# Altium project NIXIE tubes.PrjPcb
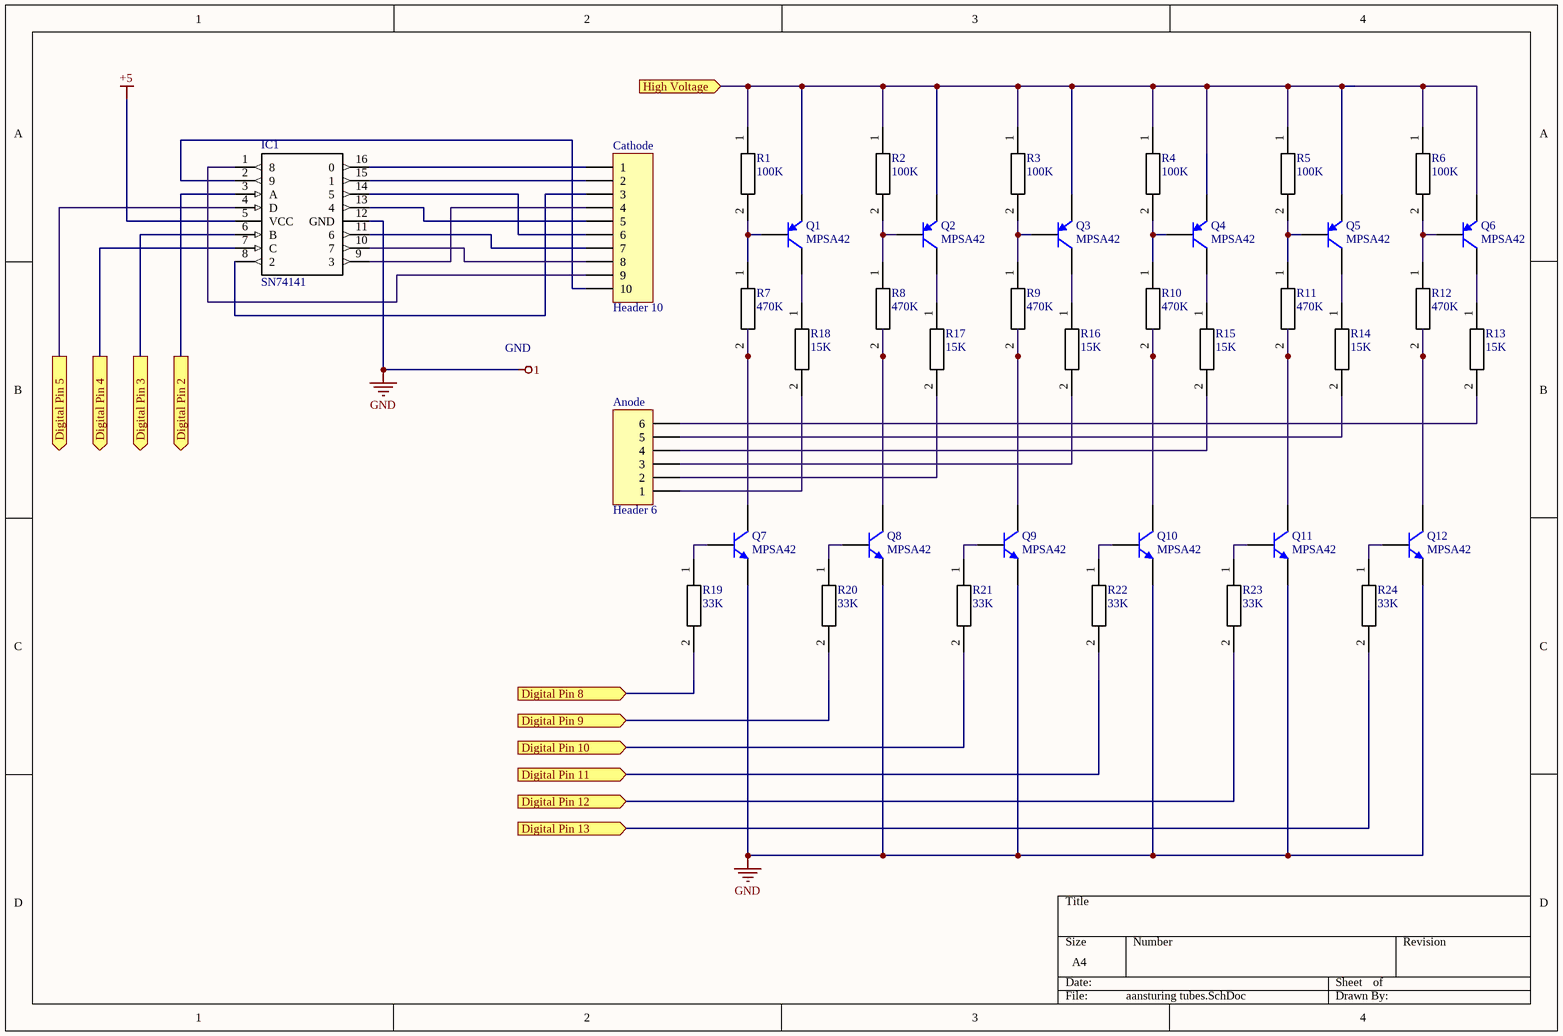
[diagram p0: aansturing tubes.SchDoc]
4 sheets, 89 parts. Net scope: flat (ports and power ports of the same name join across sheets).
Board files: PCB1-sturing.PcbDoc, PCB2-Tubes.PcbDoc
Sheets:
  aansturing tubes.SchDoc
  high voltage.SchDoc
  low voltage + controller.SchDoc
  Tubes.SchDoc

## Sheet aansturing tubes.SchDoc
size A4

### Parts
Anode  Header 6  [HDR1X6]
Cathode  Header 10  [HDR1X10]
IC1  SN74141  [DIP787W53P279L2176H508Q16N]
Q1  MPSA42  [TO-92A]
Q2  MPSA42  [TO-92A]
Q3  MPSA42  [TO-92A]
Q4  MPSA42  [TO-92A]
Q5  MPSA42  [TO-92A]
Q6  MPSA42  [TO-92A]
Q7  MPSA42  [TO-92A]
Q8  MPSA42  [TO-92A]
Q9  MPSA42  [TO-92A]
Q10  MPSA42  [TO-92A]
Q11  MPSA42  [TO-92A]
Q12  MPSA42  [TO-92A]
R1  100K  [RESC3116X65N]
R2  100K  [RESC3116X65N]
R3  100K  [RESC3116X65N]
R4  100K  [RESC3116X65N]
R5  100K  [RESC3116X65N]
R6  100K  [RESC3116X65N]
R7  470K  [RESC3116X65N]
R8  470K  [RESC3116X65N]
R9  470K  [RESC3116X65N]
R10  470K  [RESC3116X65N]
R11  470K  [RESC3116X65N]
R12  470K  [RESC3116X65N]
R13  15K  [RESAD1590W60L630D240]
R14  15K  [RESAD1590W60L630D240]
R15  15K  [RESAD1590W60L630D240]
R16  15K  [RESAD1590W60L630D240]
R17  15K  [RESAD1590W60L630D240]
R18  15K  [RESAD1590W60L630D240]
R19  33K  [RESC3116X65N]
R20  33K  [RESC3116X65N]
R21  33K  [RESC3116X65N]
R22  33K  [RESC3116X65N]
R23  33K  [RESC3116X65N]
R24  33K  [RESC3116X65N]

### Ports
Digital Pin 2 (out), Digital Pin 3 (out), Digital Pin 4 (out), Digital Pin 5 (out), Digital Pin 8 (in), Digital Pin 9 (in), Digital Pin 10 (in), Digital Pin 11 (in), Digital Pin 12 (in), Digital Pin 13 (in), High Voltage (in)

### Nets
1: IC1.12(GND) Q7.1(E) Q8.1(E) Q9.1(E) Q10.1(E) Q11.1(E) Q12.1(E)  [also labelled GND]
+5: IC1.5(VCC)
NetAnode_1: Anode.1 R18.2
NetAnode_2: Anode.2 R17.2
NetAnode_3: Anode.3 R16.2
NetAnode_4: Anode.4 R15.2
NetAnode_5: Anode.5 R14.2
NetAnode_6: Anode.6 R13.2
NetC1_1: Q1.1(E) Q2.1(E) Q3.1(E) Q4.1(E) Q5.1(E) Q6.1(E) R1.1 R2.1 R3.1 R4.1 R5.1 R6.1 ; port High Voltage
NetCathode_1: Cathode.1 IC1.16(0)
NetCathode_2: Cathode.2 IC1.15(1)
NetCathode_3: Cathode.3 IC1.8(2)
NetCathode_4: Cathode.4 IC1.9(3)
NetCathode_5: Cathode.5 IC1.13(4)
NetCathode_6: Cathode.6 IC1.14(5)
NetCathode_7: Cathode.7 IC1.11(6)
NetCathode_8: Cathode.8 IC1.10(7)
NetCathode_9: Cathode.9 IC1.1(8)
NetCathode_10: Cathode.10 IC1.2(9)
NetIC1_3: IC1.3(A) ; port Digital Pin 2
NetIC1_4: IC1.4(D) ; port Digital Pin 5
NetIC1_6: IC1.6(B) ; port Digital Pin 3
NetIC1_7: IC1.7(C) ; port Digital Pin 4
NetIC3_14: R19.2 ; port Digital Pin 8
NetIC3_15: R20.2 ; port Digital Pin 9
NetIC3_16: R21.2 ; port Digital Pin 10
NetIC3_17: R22.2 ; port Digital Pin 11
NetIC3_18: R23.2 ; port Digital Pin 12
NetIC3_19: R24.2 ; port Digital Pin 13
NetQ1_2: Q1.2(B) R1.2 R7.1
NetQ1_3: Q1.3(C) R18.1
NetQ2_2: Q2.2(B) R2.2 R8.1
NetQ2_3: Q2.3(C) R17.1
NetQ3_2: Q3.2(B) R3.2 R9.1
NetQ3_3: Q3.3(C) R16.1
NetQ4_2: Q4.2(B) R4.2 R10.1
NetQ4_3: Q4.3(C) R15.1
NetQ5_2: Q5.2(B) R5.2 R11.1
NetQ5_3: Q5.3(C) R14.1
NetQ6_2: Q6.2(B) R6.2 R12.1
NetQ6_3: Q6.3(C) R13.1
NetQ7_2: Q7.2(B) R19.1
NetQ7_3: Q7.3(C) R7.2
NetQ8_2: Q8.2(B) R20.1
NetQ8_3: Q8.3(C) R8.2
NetQ9_2: Q9.2(B) R21.1
NetQ9_3: Q9.3(C) R9.2
NetQ10_2: Q10.2(B) R22.1
NetQ10_3: Q10.3(C) R10.2
NetQ11_2: Q11.2(B) R23.1
NetQ11_3: Q11.3(C) R11.2
NetQ12_2: Q12.2(B) R24.1
NetQ12_3: Q12.3(C) R12.2

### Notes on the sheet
- GND

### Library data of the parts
Anode = Header 6: Header, 6-Pin
Cathode = Header 10: Header, 10-Pin
IC1 = SN74141: Integrated Circuit; Manufacturer_Name: Texas Instruments
Q1-Q6 = 2N3906: PNP General Purpose Amplifier
Q7-Q12 = 2N3904: NPN General Purpose Amplifier
R1-R12 R19-R24 = RC1206JR-07_10KL: Resistor; Manufacturer_Name: YAGEO (PHYCOMP); Manufacturer_Part_Number: RC1206JR-07 10KL
R13-R18 = MF0207FTE52-10K: Resistor; Manufacturer_Name: YAGEO (PHYCOMP)

## Sheet high voltage.SchDoc
size A4
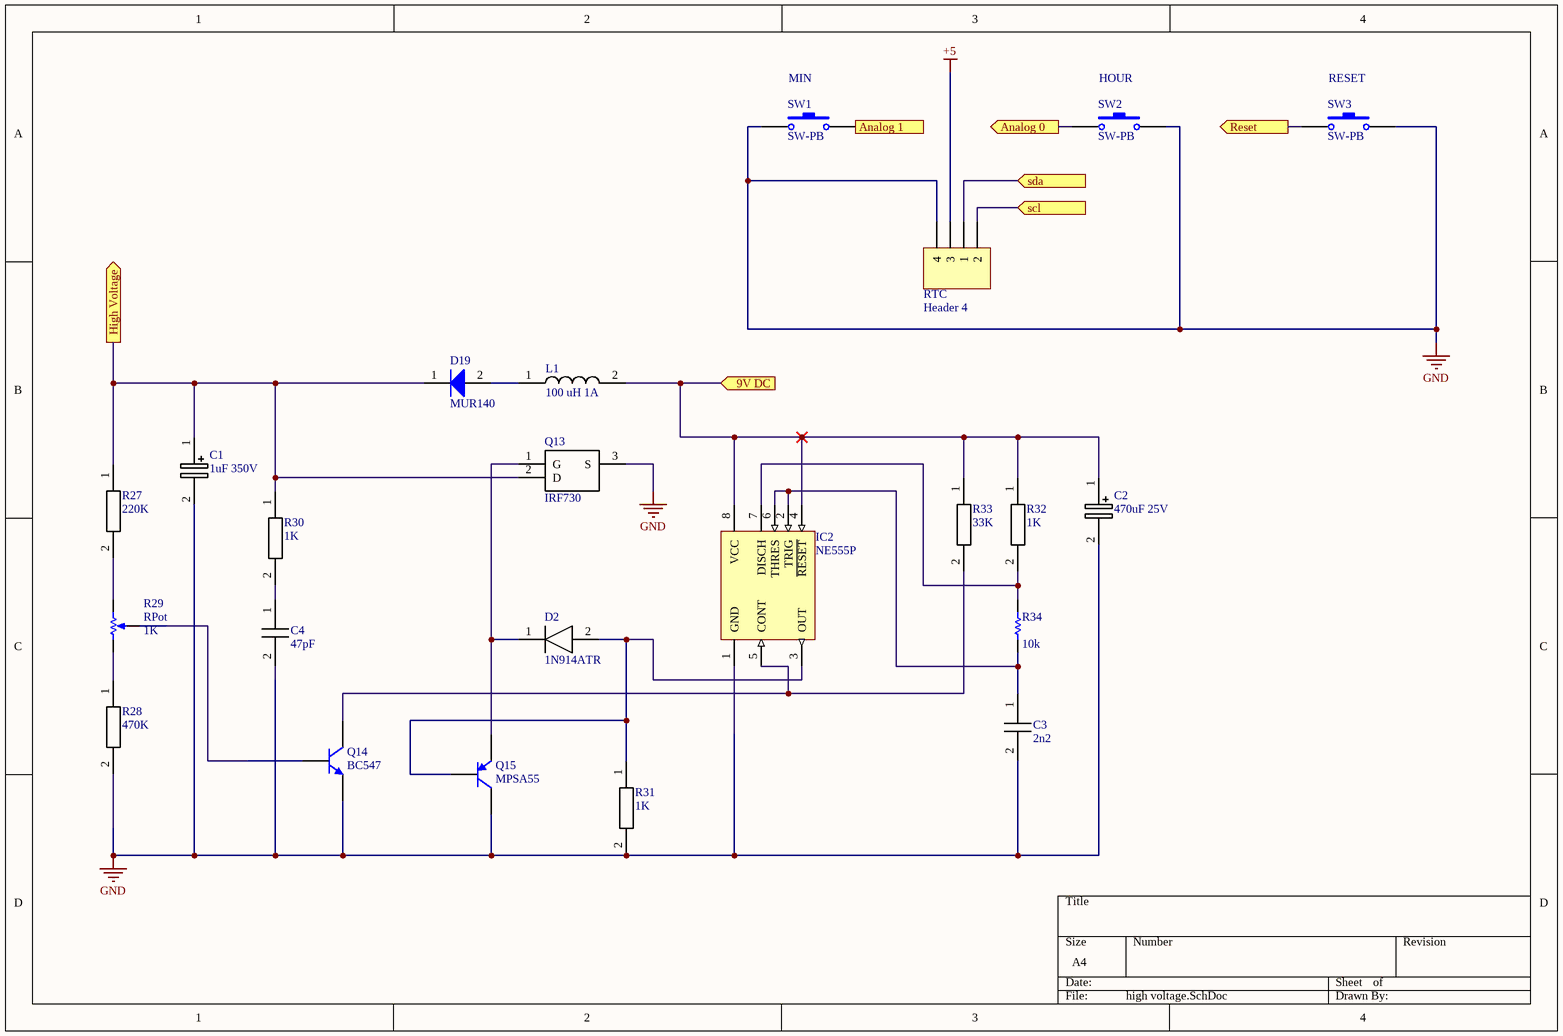
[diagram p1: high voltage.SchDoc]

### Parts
C1  1uF 350V  [CAPPRD350W52D800H1300]
C2  470uF 25V  [CAPPRD350W52D800H1300]
C3  2n2  [CAPC3216X95N]
C4  47pF  [CAPC3216X95N]
D2  1N914ATR  [DIOAD1068W53L380D172]
D19  MUR140  [ONSC-AXIAL_LEAD-2-59-10_P]
IC2  NE555P  [P0008A]
L1  100 uH 1A  [WE-TI_8012B89]
Q13  IRF730  [TO254P465X1024X1989-3P]
Q14  BC547  [TO-92A]
Q15  MPSA55  [TO-92A]
R27  220K  [RESAD1590W60L630D240]
R28  470K  [RESAD1590W60L630D240]
R29  RPot  value 1K  [VR5]
R30  1K  [RESAD1590W60L630D240]
R31  1K  [RESAD1590W60L630D240]
R32  1K  [RESAD1590W60L630D240]
R33  33K  [RESAD1590W60L630D240]
R34  value 10k  [AXIAL-0.3]  (hidden comment: Res1)
RTC  Header 4  [HDR1X4]
SW1  SW-PB  [SPST-2]
SW2  SW-PB  [SPST-2]
SW3  SW-PB  [SPST-2]

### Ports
9V DC (in), Analog 0 (out), Analog 1 (out), High Voltage (out), Reset (out), scl (in), sda (in)

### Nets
+5: RTC.3
GND: C1.2(-) C2.2(-) C3.2 C4.2 IC2.1(GND) Q13.3(S) Q14.1(E) Q15.3(C) R28.2 R31.2 RTC.4 SW1.1 SW2.2 SW3.2  [project net 1]
NetC1_1: C1.1(+) D19.1(K) Q13.2(D) R27.1 R30.1 ; port High Voltage
NetC2_1: C2.1(+) IC2.4(~{RESET}) IC2.8(VCC) L1.2 R32.1 R33.1 ; port 9V DC
NetC3_1: C3.1 IC2.2(TRIG) IC2.6(THRES) R34.1
NetC4_1: C4.1 R30.2
NetD2_1: D2.1(K) Q13.1(G) Q15.1(E)
NetD2_2: D2.2(A) IC2.3(OUT) Q15.2(B) R31.1
NetD19_2: D19.2(A) L1.1
NetIC2_5: IC2.5(CONT) Q14.3(C) R33.2
NetIC2_7: IC2.7(DISCH) R32.2 R34.2
NetIC3_1: SW3.1 ; port Reset
NetIC3_23: SW1.2 ; port Analog 1
NetIC3_24: SW2.1 ; port Analog 0
NetIC3_27: RTC.1 ; port sda
NetIC3_28: RTC.2 ; port scl
NetQ14_2: Q14.2(B) R29.3(TAP)
NetR27_2: R27.2 R29.2(BOT)
NetR28_1: R28.1 R29.1(TOP)

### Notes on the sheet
- (near SW1) MIN
- (near SW2) HOUR
- (near SW3) RESET

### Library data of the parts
C1 C2 = 860131274001: Capacitor Polarised; Manufacturer_Name: Wurth Elektronik
C3 = CC1206KRX7R9BB471: Capacitor; Manufacturer_Name: YAGEO (PHYCOMP)
C4 = CC1206JRNPO9BN220: Capacitor; Manufacturer_Name: YAGEO (PHYCOMP)
D2 = 1N914ATR: Diode; Manufacturer_Name: Fairchild Semiconductor
D19 = CMP-0902-00130-1: SWITCHMODE(TM) Power Rectifier, 2-Pin Axial_Lead, Pb-Free, Bulk Box; Manufacturer: On Semiconductor; IFSM Max (A): 35; Type: Ultrafast; VRRM Max (V): 400
IC2 = CMP-2000-04954-1: Precision Timer, 4.5 to 16 V, 0 to 70 degC, 8-Pin DIP, Pb-Free, Tube; Manufacturer: TexasInstruments; Maximum High Level Output Current: -200mA; Number of Internal Timers: 1; Operating Supply Voltage: 5; Maximum Low Level Output Current: 200mA; Rad Hard: No
L1 = 744743101: Inductor; Manufacturer_Name: Wurth Elektronik
Q13 = IRF730: Transistor; Manufacturer_Name: STMicroelectronics
Q14 = 2N3904: NPN General Purpose Amplifier
Q15 = 2N3906: PNP General Purpose Amplifier
R27 R28 R30-R33 = MF0207FTE52-10K: as R13 on sheet aansturing tubes
R29 = RPot: Potentiometer; Sim Note: Enter the Resistance value and the set point into parameter fields.; Set Position: 0.5
R34 = Res1: Resistor
RTC = Header 4: Header, 4-Pin
SW1-SW3 = SW-PB: Switch

## Sheet low voltage + controller.SchDoc
size A4
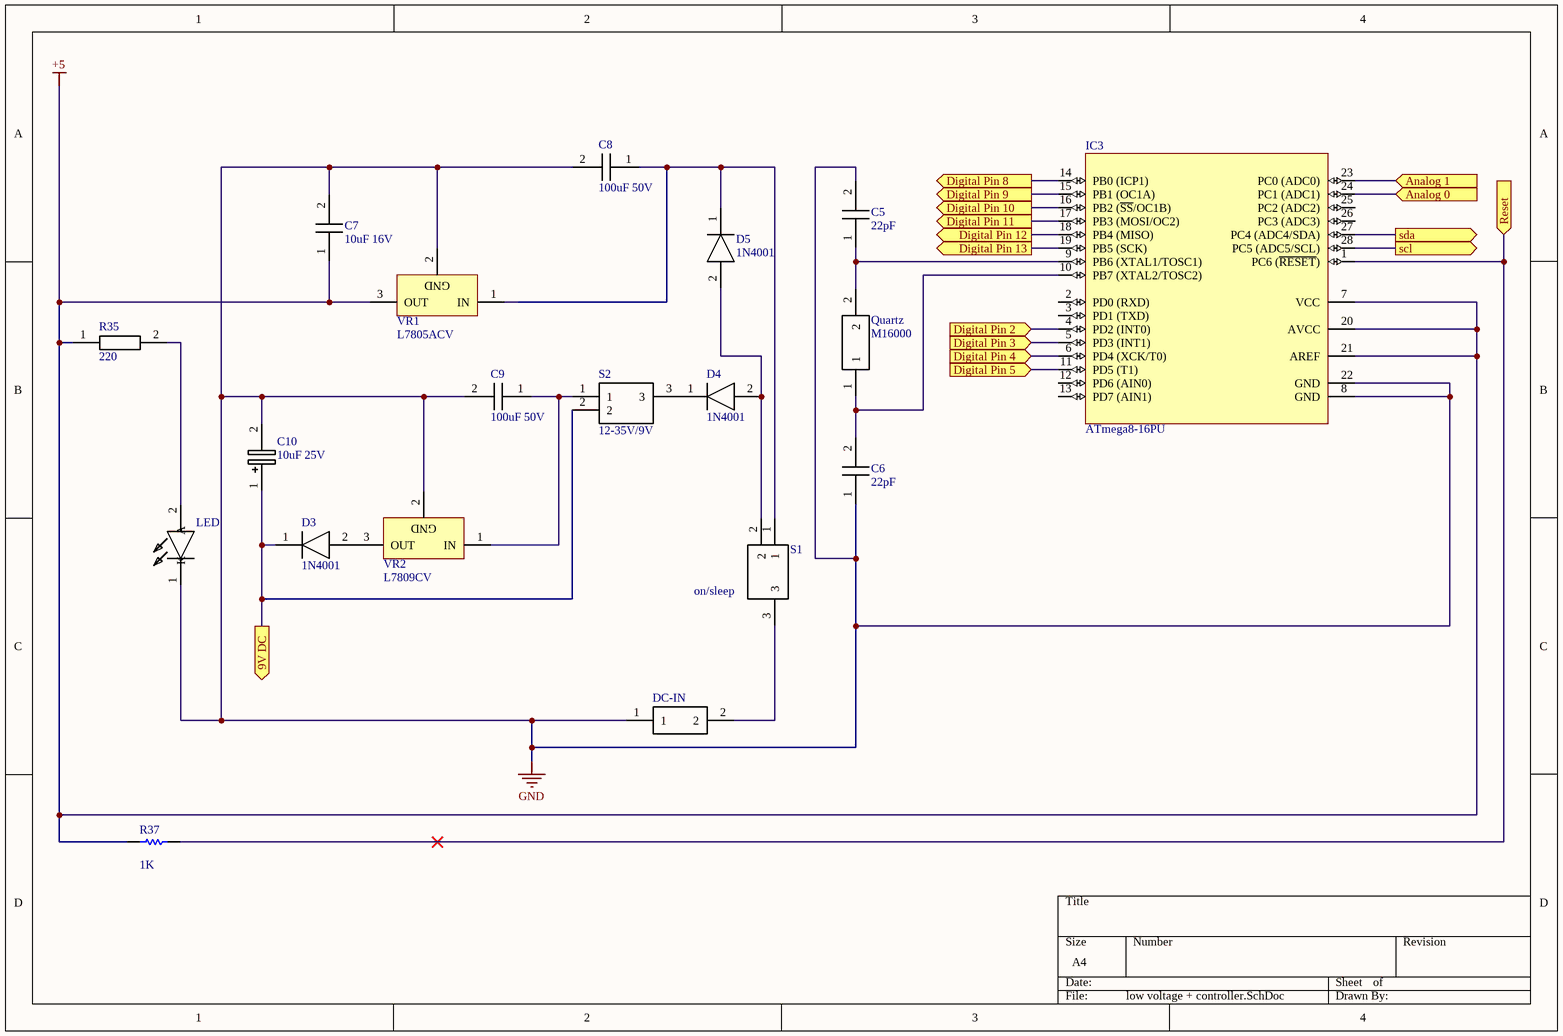
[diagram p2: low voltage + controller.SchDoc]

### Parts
C5  22pF  [CAPC3216X95N]
C6  22pF  [CAPC3216X95N]
C7  10uF 16V  [ECE-A1CKS100]
C8  100uF 50V  [860240675007]
C9  100uF 50V  [860240675007]
C10  10uF 25V  [CAPPRD150W50D400H800]
D3  1N4001  [DIOAD1410W86L470D235]
D4  1N4001  [DIOAD1410W86L470D235]
D5  1N4001  [DIOAD1410W86L470D235]
DC-IN  282836-2  [2828362]  (value not drawn)
IC3  ATmega8-16PU  [28P3]
LED  HLMP-3301  [HLMP-3301]  (value not drawn)
Quartz  M16000  [FOXSLF/200-20]
R35  220  [RESC3116X65N]
R37  value 1K  [AXIAL-0.3]  (hidden comment: Res1)
S1  on/sleep  [NK236]
S2  12-35V/9V  [NK236]
VR1  L7805ACV  [TO220]
VR2  L7809CV  [TO220]

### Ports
9V DC (out), Analog 0 (in), Analog 1 (in), Digital Pin 2 (in), Digital Pin 3 (in), Digital Pin 4 (in), Digital Pin 5 (in), Digital Pin 8 (out), Digital Pin 9 (out), Digital Pin 10 (out), Digital Pin 11 (out), Digital Pin 12 (out), Digital Pin 13 (out), Reset (in), scl (out), sda (out)

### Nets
+5: C7.1 IC3.7(VCC) IC3.20(AVCC) IC3.21(AREF) R35.1 R37.1 VR1.3(OUT)
GND: C5.2 C6.1 C7.2 C8.2(+) C9.2(+) C10.2(-) DC-IN.1 IC3.8(GND) IC3.22(GND) LED.1(K) VR1.2(GND) VR2.2(GND)  [project net 1]
NetC2_1: C10.1(+) D3.1(K) S2.2 ; port 9V DC
NetC5_1: C5.1 IC3.9(PB6_(XTAL1/TOSC1)) Quartz.2
NetC6_2: C6.2 IC3.10(PB7_(XTAL2/TOSC2)) Quartz.1
NetC8_1: C8.1(-) D5.1(K) S1.1 VR1.1(IN)
NetC9_1: C9.1(-) S2.1 VR2.1(IN)
NetD3_2: D3.2(A) VR2.3(OUT)
NetD4_1: D4.1(K) S2.3
NetD4_2: D4.2(A) D5.2(A) S1.2
NetDC-IN_2: DC-IN.2 S1.3
NetIC1_3: IC3.4(PD2_(INT0)) ; port Digital Pin 2
NetIC1_4: IC3.11(PD5_(T1)) ; port Digital Pin 5
NetIC1_6: IC3.5(PD3_(INT1)) ; port Digital Pin 3
NetIC1_7: IC3.6(PD4_(XCK/T0)) ; port Digital Pin 4
NetIC3_1: IC3.1(PC6_(~{RESET})) R37.2 ; port Reset
NetIC3_14: IC3.14(PB0_(ICP1)) ; port Digital Pin 8
NetIC3_15: IC3.15(PB1_(OC1A)) ; port Digital Pin 9
NetIC3_16: IC3.16(PB2_(~{SS}/OC1B)) ; port Digital Pin 10
NetIC3_17: IC3.17(PB3_(MOSI/OC2)) ; port Digital Pin 11
NetIC3_18: IC3.18(PB4_(MISO)) ; port Digital Pin 12
NetIC3_19: IC3.19(PB5_(SCK)) ; port Digital Pin 13
NetIC3_23: IC3.23(PC0_(ADC0)) ; port Analog 1
NetIC3_24: IC3.24(PC1_(ADC1)) ; port Analog 0
NetIC3_27: IC3.27(PC4_(ADC4/SDA)) ; port sda
NetIC3_28: IC3.28(PC5_(ADC5/SCL)) ; port scl
NetLED_2: LED.2(A) R35.2

Not connected (* = marked no-connect by the designer): IC3 2(PD0_(RXD)) 3(PD1_(TXD)) 12(PD6_(AIN0)) 13(PD7_(AIN1)) 25(PC2_(ADC2)) 26(PC3_(ADC3))

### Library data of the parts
C5 C6 = CC1206JRNPO9BN220: as C4 on sheet high voltage
C7 = ECE-A1CKS100: Capacitor; Manufacturer_Name: Panasonic; Allied_Number: 70067880
C8 C9 = 860240675007: Capacitor; Manufacturer_Name: Wurth Elektronik
C10 = EEA-FC1E100: Capacitor Polarised; Manufacturer_Name: Panasonic; Allied_Number: 70256144
D3-D5 = 1N4001: Diode; Manufacturer_Name: MULTICOMP
DC-IN = 282836-2: Connector; Manufacturer_Name: TE CONNECTIVITY / BUCHANAN; Allied_Number: 70086275
IC3 = CMP-0095-00372-1: 8-bit AVR Microcontroller, 4.5-5.5V, 16MHz, 8KB Flash, 512 Bytes EEPROM, 1KB SRAM, 28-pin PDIP, Industrial Grade (-40°C to 85°C)
LED = HLMP-3301: LED; Manufacturer_Name: Avago Technologies
Quartz = FOXSLF_080: Crystal or Oscillator; Manufacturer_Name: Fox; Manufacturer_Part_Number: FOXSLF/080
R35 = RC1206JR-07_10KL: as R1 on sheet aansturing tubes
R37 = Res1: Resistor
S1 S2 = NK236: Switch; Manufacturer_Name: Apem
VR1 = CMP-0244-00484-1: Positive Voltage Regulator, 5V, 3-Pin TO-220
VR2 = CMP-0244-00459-1: Positive Voltage Regulator, 9V, 3-Pin TO-220

## Sheet Tubes.SchDoc
size A4
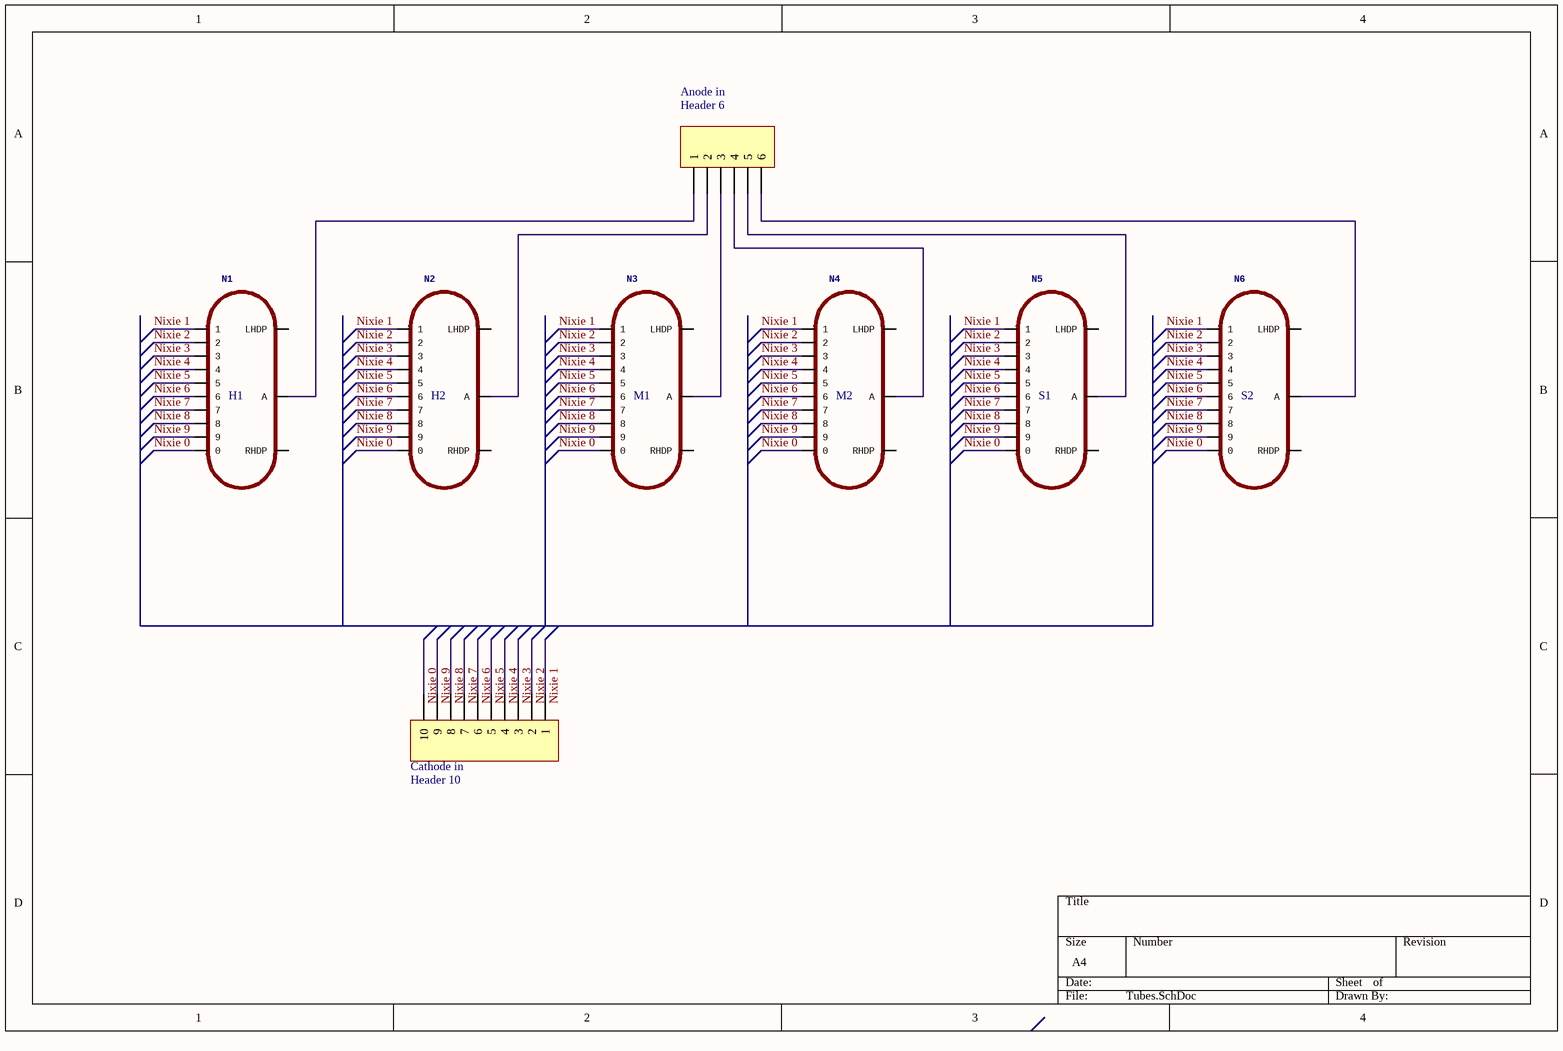
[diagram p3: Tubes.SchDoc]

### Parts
Anode_in  Header 6  [HDR1X6]
Cathode_in  Header 10  [HDR1X10]
N1  H1  [IN-14]
N2  H2  [IN-14]
N3  M1  [IN-14]
N4  M2  [IN-14]
N5  S1  [IN-14]
N6  S2  [IN-14]

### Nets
Nixie 0: Cathode_in.10 N1.0 N2.0 N3.0 N4.0 N5.0 N6.0
Nixie 1: Cathode_in.1 N1.1 N2.1 N3.1 N4.1 N5.1 N6.1
Nixie 2: Cathode_in.2 N1.2 N2.2 N3.2 N4.2 N5.2 N6.2
Nixie 3: Cathode_in.3 N1.3 N2.3 N3.3 N4.3 N5.3 N6.3
Nixie 4: Cathode_in.4 N1.4 N2.4 N3.4 N4.4 N5.4 N6.4
Nixie 5: Cathode_in.5 N1.5 N2.5 N3.5 N4.5 N5.5 N6.5
Nixie 6: Cathode_in.6 N1.6 N2.6 N3.6 N4.6 N5.6 N6.6
Nixie 7: Cathode_in.7 N1.7 N2.7 N3.7 N4.7 N5.7 N6.7
Nixie 8: Cathode_in.8 N1.8 N2.8 N3.8 N4.8 N5.8 N6.8
Nixie 9: Cathode_in.9 N1.9 N2.9 N3.9 N4.9 N5.9 N6.9
NetAnode_in_1: Anode_in.1 N1.A
NetAnode_in_2: Anode_in.2 N2.A
NetAnode_in_3: Anode_in.3 N3.A
NetAnode_in_4: Anode_in.4 N4.A
NetAnode_in_5: Anode_in.5 N5.A
NetAnode_in_6: Anode_in.6 N6.A

Not connected (* = marked no-connect by the designer): N1 LHDP RHDP; N2 LHDP RHDP; N3 LHDP RHDP; N4 LHDP RHDP; N5 LHDP RHDP; N6 LHDP RHDP

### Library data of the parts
Anode_in = Header 6: Header, 6-Pin
Cathode_in = Header 10: Header, 10-Pin
N1-N6 = IN-14: GateName_1: G$1

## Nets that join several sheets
1: aansturing tubes (7 pins), high voltage (14 pins), low voltage + controller (12 pins)
+5: aansturing tubes (IC1.5), high voltage (RTC.3), low voltage + controller (7 pins)
NetC1_1: aansturing tubes (12 pins), high voltage (5 pins)
NetC2_1: high voltage (6 pins), low voltage + controller (C10.1 D3.1 S2.2)
NetIC1_3: aansturing tubes (IC1.3), low voltage + controller (IC3.4)
NetIC1_4: aansturing tubes (IC1.4), low voltage + controller (IC3.11)
NetIC1_6: aansturing tubes (IC1.6), low voltage + controller (IC3.5)
NetIC1_7: aansturing tubes (IC1.7), low voltage + controller (IC3.6)
NetIC3_1: high voltage (SW3.1), low voltage + controller (IC3.1 R37.2)
NetIC3_14: aansturing tubes (R19.2), low voltage + controller (IC3.14)
NetIC3_15: aansturing tubes (R20.2), low voltage + controller (IC3.15)
NetIC3_16: aansturing tubes (R21.2), low voltage + controller (IC3.16)
NetIC3_17: aansturing tubes (R22.2), low voltage + controller (IC3.17)
NetIC3_18: aansturing tubes (R23.2), low voltage + controller (IC3.18)
NetIC3_19: aansturing tubes (R24.2), low voltage + controller (IC3.19)
NetIC3_23: high voltage (SW1.2), low voltage + controller (IC3.23)
NetIC3_24: high voltage (SW2.1), low voltage + controller (IC3.24)
NetIC3_27: high voltage (RTC.1), low voltage + controller (IC3.27)
NetIC3_28: high voltage (RTC.2), low voltage + controller (IC3.28)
